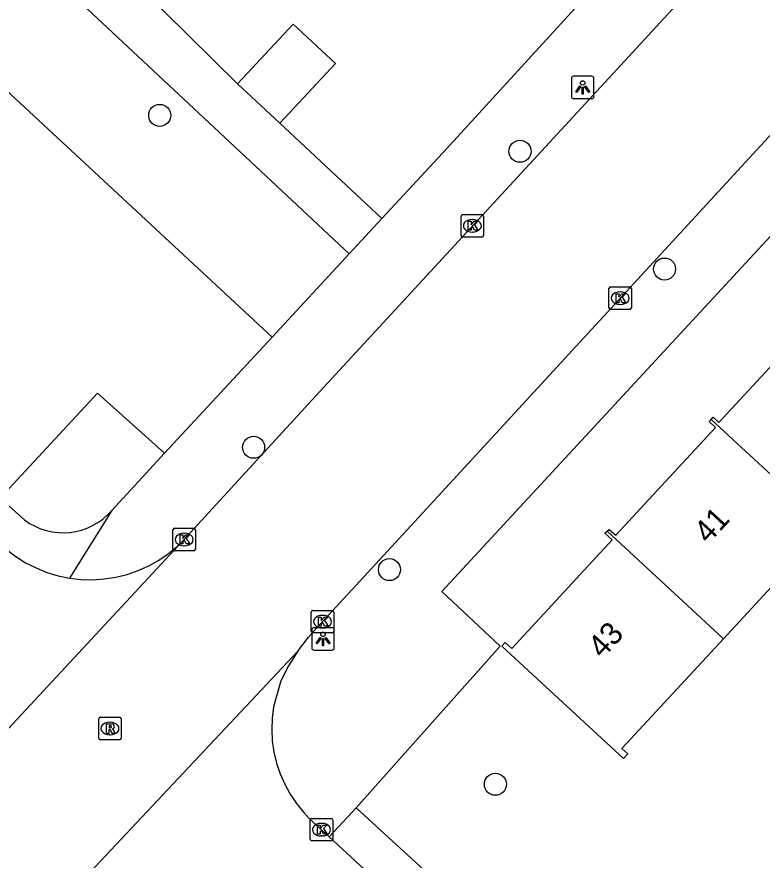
# Model space of a CAD drawing. Extents: x 159222 to 160346, y 381249 to 382166.
# Drawn here: x 159821.69 to 159854.8, y 381588.83 to 381626.29 of the extents above; entities that cross this region are included whole.
import ezdxf

# ---------------------------------------------------------------- set-up
doc = ezdxf.new("R2010")
doc.units = 0
for name, color, linetype in [('IMGEO_Boom', 7, 'Continuous'), ('IMGEO_Groenvoorziening', 7, 'Continuous'), ('IMGEO_Kolk', 7, 'Continuous'), ('IMGEO_Lichtpunt', 7, 'Continuous'), ('IMGEO_Pand', 7, 'Continuous'), ('IMGEO_Pand_nummerreeks', 7, 'Continuous'), ('IMGEO_Rijbaan_lokaal_open', 7, 'Continuous'), ('IMGEO_Rioolput', 7, 'Continuous'), ('IMGEO_Voetpad_open', 7, 'Continuous')]:
    doc.layers.add(name, color=color, linetype=linetype)

msp = doc.modelspace()

# ---------------------------------------------------------------- linework, layer by layer
at = {"layer": 'IMGEO_Boom'}
for centre in [(159828.037, 381621.916), (159844.044, 381620.323), (159850.466, 381615.092), (159832.21, 381607.17), (159838.245, 381601.737), (159842.95, 381592.2)]:
    msp.add_circle(centre, 0.489, dxfattribs=at)
at = {"layer": 'IMGEO_Groenvoorziening'}
for points in [[(159802.529, 381622.003), (159811.633, 381631.939), (159833.028, 381612.068)], [(159828.247, 381606.909), (159825.276, 381609.576), (159820.934, 381604.918)]]:
    msp.add_lwpolyline(points, dxfattribs=at)
at = {"layer": 'IMGEO_Kolk'}
for p, q in [((159841.502, 381617.511), (159842.354, 381617.511)), ((159841.427, 381616.585), (159841.427, 381617.437)), ((159841.915, 381617.291), (159841.94, 381617.291)), ((159842.428, 381617.437), (159842.428, 381616.585)), ((159841.938, 381616.731), (159841.913, 381616.731)), ((159842.354, 381616.511), (159841.502, 381616.511)), ((159847.996, 381613.37), (159847.996, 381614.222)), ((159848.071, 381614.296), (159848.923, 381614.296)), ((159848.997, 381614.222), (159848.997, 381613.37)), ((159848.484, 381614.076), (159848.509, 381614.076)), ((159848.507, 381613.516), (159848.482, 381613.516)), ((159848.923, 381613.296), (159848.071, 381613.296)), ((159828.625, 381602.649), (159828.625, 381603.501)), ((159828.7, 381603.575), (159829.552, 381603.575)), ((159829.113, 381603.355), (159829.138, 381603.355)), ((159829.626, 381603.501), (159829.626, 381602.649)), ((159829.552, 381602.575), (159828.7, 381602.575)), ((159829.136, 381602.795), (159829.111, 381602.795)), ((159834.846, 381599.926), (159835.698, 381599.926)), ((159834.771, 381599), (159834.771, 381599.852)), ((159835.259, 381599.706), (159835.284, 381599.706)), ((159835.772, 381599.852), (159835.772, 381599)), ((159835.282, 381599.146), (159835.257, 381599.146)), ((159835.698, 381598.926), (159834.846, 381598.926)), ((159834.726, 381589.758), (159834.726, 381590.61)), ((159834.801, 381590.684), (159835.653, 381590.684)), ((159835.727, 381590.61), (159835.727, 381589.758)), ((159835.214, 381590.464), (159835.239, 381590.464)), ((159835.237, 381589.904), (159835.212, 381589.904)), ((159835.653, 381589.684), (159834.801, 381589.684))]:
    msp.add_line(p, q, dxfattribs=at)
for points in [[(159841.502, 381617.511), (159842.354, 381617.511)], [(159841.427, 381616.585), (159841.427, 381617.437)], [(159841.748, 381617.211), (159841.871, 381617.211), (159841.871, 381617.06), (159842.001, 381617.211), (159842.165, 381617.211), (159842.019, 381617.06), (159842.172, 381616.811), (159842.02, 381616.811), (159841.935, 381616.975), (159841.871, 381616.908), (159841.871, 381616.811), (159841.748, 381616.811), (159841.748, 381617.211)], [(159842.428, 381617.437), (159842.428, 381616.585)], [(159842.354, 381616.511), (159841.502, 381616.511)], [(159847.996, 381613.37), (159847.996, 381614.222)], [(159848.071, 381614.296), (159848.923, 381614.296)], [(159848.997, 381614.222), (159848.997, 381613.37)], [(159848.317, 381613.996), (159848.44, 381613.996), (159848.44, 381613.845), (159848.57, 381613.996), (159848.734, 381613.996), (159848.588, 381613.845), (159848.741, 381613.596), (159848.589, 381613.596), (159848.504, 381613.76), (159848.44, 381613.693), (159848.44, 381613.596), (159848.317, 381613.596), (159848.317, 381613.996)], [(159848.923, 381613.296), (159848.071, 381613.296)], [(159828.625, 381602.649), (159828.625, 381603.501)], [(159828.7, 381603.575), (159829.552, 381603.575)], [(159828.946, 381603.275), (159829.069, 381603.275), (159829.069, 381603.124), (159829.199, 381603.275), (159829.363, 381603.275), (159829.217, 381603.124), (159829.37, 381602.875), (159829.218, 381602.875), (159829.133, 381603.039), (159829.069, 381602.972), (159829.069, 381602.875), (159828.946, 381602.875), (159828.946, 381603.275)], [(159829.626, 381603.501), (159829.626, 381602.649)], [(159829.552, 381602.575), (159828.7, 381602.575)], [(159834.846, 381599.926), (159835.698, 381599.926)], [(159834.771, 381599), (159834.771, 381599.852)], [(159835.092, 381599.626), (159835.215, 381599.626), (159835.215, 381599.475), (159835.345, 381599.626), (159835.509, 381599.626), (159835.363, 381599.475), (159835.516, 381599.226), (159835.364, 381599.226), (159835.279, 381599.39), (159835.215, 381599.323), (159835.215, 381599.226), (159835.092, 381599.226), (159835.092, 381599.626)], [(159835.772, 381599.852), (159835.772, 381599)], [(159835.698, 381598.926), (159834.846, 381598.926)], [(159834.726, 381589.758), (159834.726, 381590.61)], [(159834.801, 381590.684), (159835.653, 381590.684)], [(159835.727, 381590.61), (159835.727, 381589.758)], [(159835.047, 381590.384), (159835.17, 381590.384), (159835.17, 381590.233), (159835.3, 381590.384), (159835.464, 381590.384), (159835.318, 381590.233), (159835.471, 381589.984), (159835.319, 381589.984), (159835.234, 381590.148), (159835.17, 381590.081), (159835.17, 381589.984), (159835.047, 381589.984), (159835.047, 381590.384)], [(159835.653, 381589.684), (159834.801, 381589.684)]]:
    msp.add_lwpolyline(points, dxfattribs=at)
for centre, start, end in [((159841.504, 381617.435), 91.552, 178.448), ((159841.504, 381617.435), 91.552, 178.448), ((159842.352, 381617.435), 1.552, 88.448), ((159842.352, 381617.435), 1.552, 88.448), ((159841.504, 381616.587), 181.552, 268.448), ((159841.504, 381616.587), 181.552, 268.448), ((159842.352, 381616.587), 271.552, 358.448), ((159842.352, 381616.587), 271.552, 358.448), ((159848.073, 381614.22), 91.552, 178.448), ((159848.073, 381614.22), 91.552, 178.448), ((159848.921, 381614.22), 1.552, 88.448), ((159848.921, 381614.22), 1.552, 88.448), ((159848.073, 381613.372), 181.552, 268.448), ((159848.073, 381613.372), 181.552, 268.448), ((159848.921, 381613.372), 271.552, 358.448), ((159848.921, 381613.372), 271.552, 358.448), ((159828.702, 381603.499), 91.552, 178.448), ((159828.702, 381603.499), 91.552, 178.448), ((159829.55, 381603.499), 1.552, 88.448), ((159829.55, 381603.499), 1.552, 88.448), ((159828.702, 381602.651), 181.552, 268.448), ((159828.702, 381602.651), 181.552, 268.448), ((159829.55, 381602.651), 271.552, 358.448), ((159829.55, 381602.651), 271.552, 358.448), ((159834.848, 381599.85), 91.552, 178.448), ((159834.848, 381599.85), 91.552, 178.448), ((159835.696, 381599.85), 1.552, 88.448), ((159835.696, 381599.85), 1.552, 88.448), ((159834.848, 381599.002), 181.552, 268.448), ((159834.848, 381599.002), 181.552, 268.448), ((159835.696, 381599.002), 271.552, 358.448), ((159835.696, 381599.002), 271.552, 358.448), ((159834.803, 381590.608), 91.552, 178.448), ((159834.803, 381590.608), 91.552, 178.448), ((159835.651, 381590.608), 1.552, 88.448), ((159835.651, 381590.608), 1.552, 88.448), ((159834.803, 381589.76), 181.552, 268.448), ((159834.803, 381589.76), 181.552, 268.448), ((159835.651, 381589.76), 271.552, 358.448), ((159835.651, 381589.76), 271.552, 358.448)]:
    msp.add_arc(centre, 0.0765, start, end, dxfattribs=at)
for centre, major_axis, ratio, start_param, end_param in [((159841.914, 381617.011), (-0.387, 0.002), 0.722429, 4.712389, 7.853982), ((159841.939, 381617.011), (-0.39, 0.002), 0.717154, 1.570796, 4.712389), ((159848.483, 381613.796), (-0.387, 0.002), 0.722429, 4.712389, 7.853982), ((159848.508, 381613.796), (-0.39, 0.002), 0.717154, 1.570796, 4.712389), ((159829.112, 381603.075), (-0.387, 0.002), 0.722429, 4.712389, 7.853982), ((159829.137, 381603.075), (-0.39, 0.002), 0.717154, 1.570796, 4.712389), ((159835.258, 381599.426), (-0.387, 0.002), 0.722429, 4.712389, 7.853982), ((159835.283, 381599.426), (-0.39, 0.002), 0.717154, 1.570796, 4.712389), ((159835.213, 381590.184), (-0.387, 0.002), 0.722429, 4.712389, 7.853982), ((159835.238, 381590.184), (-0.39, 0.002), 0.717154, 1.570796, 4.712389)]:
    msp.add_ellipse(centre, major_axis=major_axis, ratio=ratio, start_param=start_param, end_param=end_param, dxfattribs=at)
at = {"layer": 'IMGEO_Lichtpunt'}
for p, q in [((159846.331, 381623.561), (159846.331, 381622.754)), ((159846.331, 381623.561), (159846.331, 381622.754)), ((159847.233, 381623.656), (159846.425, 381623.656)), ((159847.233, 381623.656), (159846.425, 381623.656)), ((159847.327, 381622.754), (159847.327, 381623.561)), ((159847.327, 381622.754), (159847.327, 381623.561)), ((159846.425, 381622.66), (159847.233, 381622.66)), ((159846.425, 381622.66), (159847.233, 381622.66)), ((159835.697, 381599.157), (159834.889, 381599.157)), ((159835.697, 381599.157), (159834.889, 381599.157)), ((159834.795, 381599.062), (159834.795, 381598.255)), ((159834.795, 381599.062), (159834.795, 381598.255)), ((159835.791, 381598.255), (159835.791, 381599.062)), ((159835.791, 381598.255), (159835.791, 381599.062)), ((159834.889, 381598.161), (159835.697, 381598.161)), ((159834.889, 381598.161), (159835.697, 381598.161))]:
    msp.add_line(p, q, dxfattribs=at)
for points in [[(159846.705, 381623.225), (159846.744, 381623.197), (159846.556, 381622.935), (159846.518, 381622.962), (159846.705, 381623.225)], [(159846.807, 381623.177), (159846.854, 381623.177), (159846.854, 381622.855), (159846.807, 381622.855), (159846.807, 381623.177)], [(159846.917, 381623.197), (159846.955, 381623.224), (159847.142, 381622.962), (159847.103, 381622.934), (159846.917, 381623.197)], [(159835.169, 381598.726), (159835.208, 381598.698), (159835.02, 381598.436), (159834.982, 381598.463), (159835.169, 381598.726)], [(159835.271, 381598.678), (159835.318, 381598.678), (159835.318, 381598.356), (159835.271, 381598.356), (159835.271, 381598.678)], [(159835.381, 381598.698), (159835.419, 381598.725), (159835.606, 381598.463), (159835.567, 381598.435), (159835.381, 381598.698)]]:
    msp.add_lwpolyline(points, dxfattribs=at)
for centre in [(159846.83, 381623.359), (159835.294, 381598.86)]:
    msp.add_circle(centre, 0.0994, dxfattribs=at)
for centre, start, end in [((159846.425, 381623.561), 90, 180), ((159846.425, 381623.561), 90, 180), ((159847.233, 381623.561), 0, 90), ((159847.233, 381623.561), 0, 90), ((159846.425, 381622.754), 180, 270), ((159846.425, 381622.754), 180, 270), ((159847.233, 381622.754), 270, 0), ((159847.233, 381622.754), 270, 360), ((159834.889, 381599.062), 90, 180), ((159834.889, 381599.062), 90, 180), ((159835.697, 381599.062), 0, 90), ((159835.697, 381599.062), 0, 90), ((159834.889, 381598.255), 180, 270), ((159834.889, 381598.255), 180, 270), ((159835.697, 381598.255), 270, 0), ((159835.697, 381598.255), 270, 360)]:
    msp.add_arc(centre, 0.0946, start, end, dxfattribs=at)
at = {"layer": 'IMGEO_Pand'}
for points in [[(159831.5, 381623.317), (159833.974, 381625.968), (159835.85, 381624.217), (159833.376, 381621.566)], [(159831.5, 381623.317), (159833.376, 381621.566)], [(159852.538, 381608.41), (159852.629, 381608.508), (159852.885, 381608.27), (159857.346, 381613.094), (159857.083, 381613.337), (159857.163, 381613.423)], [(159847.91, 381603.44), (159848.007, 381603.525), (159848.301, 381603.262), (159852.728, 381608.05), (159852.446, 381608.31), (159852.538, 381608.41)], [(159852.538, 381608.41), (159857.689, 381603.647)], [(159857.689, 381603.647), (159853.078, 381598.662)], [(159853.078, 381598.662), (159848.575, 381593.791), (159848.836, 381593.551), (159848.643, 381593.343), (159843.24, 381598.339), (159843.388, 381598.499), (159843.68, 381598.228), (159848.141, 381603.053), (159847.814, 381603.355), (159847.91, 381603.44)], [(159847.91, 381603.44), (159853.078, 381598.662)]]:
    msp.add_lwpolyline(points, dxfattribs=at)
at = {"layer": 'IMGEO_Rijbaan_lokaal_open'}
for points in [[(159829.069, 381603.011), (159835.145, 381609.655), (159853.087, 381629.109), (159862.906, 381639.713), (159865.477, 381642.489), (159867.597, 381644.778), (159870.779, 381648.232), (159872.787, 381650.412), (159884.507, 381663.136), (159884.832, 381663.574)], [(159834.176, 381598.121), (159834.644, 381598.738), (159835.165, 381599.311), (159838.508, 381602.939), (159860.89, 381627.268), (159889.697, 381658.416)], [(159799.503, 381622.862), (159820.849, 381602.985), (159821.231, 381602.635), (159821.643, 381602.321), (159822.082, 381602.045), (159822.543, 381601.81), (159823.024, 381601.616), (159823.52, 381601.466), (159824.027, 381601.361)], [(159829.069, 381603.011), (159817.636, 381590.721)], [(159824.027, 381601.361), (159824.542, 381601.302), (159825.06, 381601.289), (159825.577, 381601.322), (159826.089, 381601.402), (159826.592, 381601.527), (159827.082, 381601.696), (159827.554, 381601.908), (159828.006, 381602.162), (159828.433, 381602.455), (159828.833, 381602.785), (159829.069, 381603.011)], [(159822.853, 381586.072), (159834.176, 381598.121)], [(159834.176, 381598.121), (159833.765, 381597.464), (159833.422, 381596.79), (159833.094, 381595.642), (159833.031, 381595.141), (159833.014, 381594.637), (159833.041, 381594.133), (159833.114, 381593.634), (159833.231, 381593.143), (159833.391, 381592.664), (159833.593, 381592.202), (159833.836, 381591.76), (159834.117, 381591.341), (159834.435, 381590.949), (159834.683, 381590.686), (159835.569, 381589.866)], [(159840.646, 381585.172), (159835.569, 381589.866)]]:
    msp.add_lwpolyline(points, dxfattribs=at)
at = {"layer": 'IMGEO_Rioolput'}
for p, q in [((159825.327, 381594.252), (159825.327, 381595.104)), ((159825.402, 381595.178), (159826.254, 381595.178)), ((159826.328, 381595.104), (159826.328, 381594.252)), ((159825.815, 381594.958), (159825.84, 381594.958)), ((159825.838, 381594.398), (159825.813, 381594.398)), ((159826.254, 381594.178), (159825.402, 381594.178))]:
    msp.add_line(p, q, dxfattribs=at)
for points in [[(159825.327, 381594.252), (159825.327, 381595.104)], [(159825.402, 381595.178), (159826.254, 381595.178)], [(159826.328, 381595.104), (159826.328, 381594.252)], [(159825.916, 381594.876), (159825.664, 381594.878), (159825.664, 381594.478)], [(159825.664, 381594.478), (159825.788, 381594.478), (159825.788, 381594.64), (159825.799, 381594.64)], [(159825.842, 381594.797), (159825.788, 381594.797), (159825.788, 381594.716)], [(159825.788, 381594.716), (159825.84, 381594.716)], [(159825.846, 381594.611), (159825.917, 381594.478), (159826.057, 381594.478), (159825.992, 381594.604)], [(159826.254, 381594.178), (159825.402, 381594.178)]]:
    msp.add_lwpolyline(points, dxfattribs=at)
for centre, radius, start, end in [((159825.404, 381595.102), 0.0765, 91.552, 178.448), ((159825.404, 381595.102), 0.0765, 91.552, 178.448), ((159826.252, 381595.102), 0.0765, 1.552, 88.448), ((159826.252, 381595.102), 0.0765, 1.552, 88.448), ((159825.798, 381594.587), 0.0533, 26.0293, 88.6989), ((159825.824, 381594.905), 0.19, 274.7715, 282.9687), ((159825.848, 381594.701), 0.0964, 77.0061, 93.1865), ((159825.862, 381594.758), 0.0378, 276.6634, 79.6772), ((159825.915, 381594.766), 0.109, 350.3612, 89.416), ((159825.913, 381594.766), 0.112, 277.5842, 350.9817), ((159825.897, 381594.551), 0.108, 29.5134, 73.7905), ((159825.404, 381594.254), 0.0765, 181.552, 268.448), ((159825.404, 381594.254), 0.0765, 181.552, 268.448), ((159826.252, 381594.254), 0.0765, 271.552, 358.448), ((159826.252, 381594.254), 0.0765, 271.552, 358.448)]:
    msp.add_arc(centre, radius, start, end, dxfattribs=at)
for centre, major_axis, ratio, start_param, end_param in [((159825.814, 381594.678), (-0.387, 0.002), 0.722429, 4.712389, 7.853982), ((159825.839, 381594.678), (-0.39, 0.002), 0.717154, 1.570796, 4.712389)]:
    msp.add_ellipse(centre, major_axis=major_axis, ratio=ratio, start_param=start_param, end_param=end_param, dxfattribs=at)
at = {"layer": 'IMGEO_Voetpad_open'}
for points in [[(159836.759, 381591.155), (159843.162, 381598.335), (159840.577, 381600.766), (159891.859, 381656.228)], [(159836.458, 381615.77), (159831.37, 381620.522), (159810.981, 381639.573), (159798.344, 381625.917)], [(159837.909, 381617.335), (159840.613, 381620.254), (159850.934, 381631.546)], [(159827.134, 381627.623), (159831.5, 381623.317)], [(159833.376, 381621.566), (159837.909, 381617.335)], [(159837.909, 381617.335), (159836.458, 381615.77)], [(159836.458, 381615.77), (159833.028, 381612.068)], [(159833.028, 381612.068), (159828.247, 381606.909)], [(159828.247, 381606.909), (159825.907, 381604.369)], [(159822.03, 381603.951), (159820.934, 381604.918)], [(159825.907, 381604.369), (159824.027, 381601.361)], [(159835.569, 381589.866), (159836.759, 381591.155)], [(159836.759, 381591.155), (159854.989, 381574.45)]]:
    msp.add_lwpolyline(points, dxfattribs=at)
msp.add_arc((159823.747, 381606.21), 2.838, 232.7554, 319.5518, dxfattribs=at)

# ---------------------------------------------------------------- texts
at = {"layer": 'IMGEO_Pand_nummerreeks'}
for s, p in [('41', (159852.408, 381602.846)), ('43', (159847.699, 381597.745))]:
    msp.add_text(s, height=1, rotation=47.2849, dxfattribs=at).set_placement(p)

doc.saveas('drawing.dxf')
